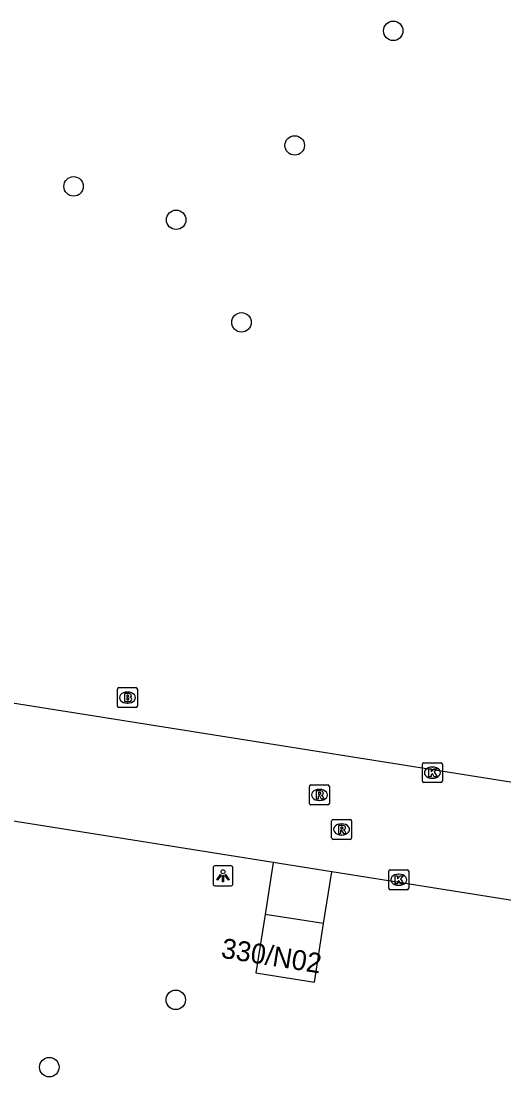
# Model space of a CAD drawing. Extents: x 154324 to 155743, y 382939 to 384183.
# Drawn here: x 155280.3 to 155304.6, y 383376.4 to 383429.5 of the extents above; entities that cross this region are included whole.
import ezdxf

# ---------------------------------------------------------------- set-up
doc = ezdxf.new("R2010")
doc.units = 0
for name, color, linetype in [('IMGEO_Boom', 7, 'Continuous'), ('IMGEO_Brandkraan', 7, 'Continuous'), ('IMGEO_Kolk', 7, 'Continuous'), ('IMGEO_Lichtpunt', 7, 'Continuous'), ('IMGEO_Pand', 7, 'Continuous'), ('IMGEO_Pand_nummerreeks', 7, 'Continuous'), ('IMGEO_Rijbaan_lokaal_gesloten', 7, 'Continuous'), ('IMGEO_Rioolput', 7, 'Continuous'), ('IMGEO_Voetpad_open', 7, 'Continuous')]:
    doc.layers.add(name, color=color, linetype=linetype)

msp = doc.modelspace()

# ---------------------------------------------------------------- linework, layer by layer
at = {"layer": 'IMGEO_Boom'}
for centre in [(155299.009, 383428.969), (155294.061, 383423.212), (155282.955, 383421.154), (155288.107, 383419.476), (155291.389, 383414.322), (155288.087, 383380.284), (155281.736, 383376.901)]:
    msp.add_circle(centre, 0.489, dxfattribs=at)
at = {"layer": 'IMGEO_Brandkraan'}
for p, q in [((155285.236, 383395.968), (155286.088, 383395.968)), ((155285.161, 383395.042), (155285.161, 383395.894)), ((155285.649, 383395.748), (155285.674, 383395.748)), ((155286.162, 383395.894), (155286.162, 383395.042)), ((155286.088, 383394.968), (155285.236, 383394.968)), ((155285.672, 383395.188), (155285.647, 383395.188))]:
    msp.add_line(p, q, dxfattribs=at)
for points in [[(155285.236, 383395.968), (155286.088, 383395.968)], [(155285.161, 383395.042), (155285.161, 383395.894)], [(155285.509, 383395.668), (155285.509, 383395.268), (155285.722, 383395.268)], [(155285.74, 383395.668), (155285.509, 383395.668)], [(155285.688, 383395.587), (155285.634, 383395.587), (155285.634, 383395.511)], [(155285.634, 383395.511), (155285.687, 383395.511)], [(155285.696, 383395.435), (155285.634, 383395.435), (155285.634, 383395.354)], [(155286.162, 383395.894), (155286.162, 383395.042)], [(155286.088, 383394.968), (155285.236, 383394.968)], [(155285.634, 383395.354), (155285.696, 383395.354)]]:
    msp.add_lwpolyline(points, dxfattribs=at)
for centre, radius, start, end in [((155285.238, 383395.892), 0.0765, 91.552, 178.448), ((155285.238, 383395.892), 0.0765, 91.552, 178.448), ((155286.086, 383395.892), 0.0765, 1.552, 88.448), ((155286.086, 383395.892), 0.0765, 1.552, 88.448), ((155285.689, 383395.549), 0.0379, 267.8285, 90.9355), ((155285.697, 383395.394), 0.0404, 269.8759, 90.5077), ((155285.744, 383395.523), 0.145, 59.4692, 91.5367), ((155285.769, 383395.57), 0.0922, 285.5137, 58.1501), ((155285.774, 383395.378), 0.105, 301.3115, 78.989), ((155285.238, 383395.044), 0.0765, 181.552, 268.448), ((155285.238, 383395.044), 0.0765, 181.552, 268.448), ((155285.728, 383395.519), 0.251, 268.6676, 293.5347), ((155286.086, 383395.044), 0.0765, 271.552, 358.448), ((155286.086, 383395.044), 0.0765, 271.552, 358.448)]:
    msp.add_arc(centre, radius, start, end, dxfattribs=at)
for centre, major_axis, ratio, start_param, end_param in [((155285.648, 383395.468), (-0.387, 0.002), 0.722429, 4.712389, 7.853982), ((155285.673, 383395.468), (-0.39, 0.002), 0.717154, 1.570796, 4.712389)]:
    msp.add_ellipse(centre, major_axis=major_axis, ratio=ratio, start_param=start_param, end_param=end_param, dxfattribs=at)
at = {"layer": 'IMGEO_Kolk'}
for p, q in [((155300.473, 383391.27), (155300.473, 383392.122)), ((155300.548, 383392.196), (155301.4, 383392.196)), ((155300.961, 383391.976), (155300.986, 383391.976)), ((155301.474, 383392.122), (155301.474, 383391.27)), ((155301.4, 383391.196), (155300.548, 383391.196)), ((155300.984, 383391.416), (155300.959, 383391.416)), ((155298.784, 383385.89), (155298.784, 383386.742)), ((155298.859, 383386.816), (155299.711, 383386.816)), ((155299.272, 383386.596), (155299.297, 383386.596)), ((155299.785, 383386.742), (155299.785, 383385.89)), ((155299.295, 383386.036), (155299.27, 383386.036)), ((155299.711, 383385.816), (155298.859, 383385.816))]:
    msp.add_line(p, q, dxfattribs=at)
for points in [[(155300.473, 383391.27), (155300.473, 383392.122)], [(155300.548, 383392.196), (155301.4, 383392.196)], [(155300.794, 383391.896), (155300.917, 383391.896), (155300.917, 383391.745), (155301.047, 383391.896), (155301.211, 383391.896), (155301.065, 383391.745), (155301.218, 383391.496), (155301.066, 383391.496), (155300.981, 383391.66), (155300.917, 383391.593), (155300.917, 383391.496), (155300.794, 383391.496), (155300.794, 383391.896)], [(155301.474, 383392.122), (155301.474, 383391.27)], [(155301.4, 383391.196), (155300.548, 383391.196)], [(155298.784, 383385.89), (155298.784, 383386.742)], [(155298.859, 383386.816), (155299.711, 383386.816)], [(155299.105, 383386.516), (155299.228, 383386.516), (155299.228, 383386.365), (155299.358, 383386.516), (155299.522, 383386.516), (155299.376, 383386.365), (155299.529, 383386.116), (155299.377, 383386.116), (155299.292, 383386.28), (155299.228, 383386.213), (155299.228, 383386.116), (155299.105, 383386.116), (155299.105, 383386.516)], [(155299.785, 383386.742), (155299.785, 383385.89)], [(155299.711, 383385.816), (155298.859, 383385.816)]]:
    msp.add_lwpolyline(points, dxfattribs=at)
for centre, start, end in [((155300.55, 383392.12), 91.552, 178.448), ((155300.55, 383392.12), 91.552, 178.448), ((155301.398, 383392.12), 1.552, 88.448), ((155301.398, 383392.12), 1.552, 88.448), ((155300.55, 383391.272), 181.552, 268.448), ((155300.55, 383391.272), 181.552, 268.448), ((155301.398, 383391.272), 271.552, 358.448), ((155301.398, 383391.272), 271.552, 358.448), ((155298.861, 383386.74), 91.552, 178.448), ((155298.861, 383386.74), 91.552, 178.448), ((155299.709, 383386.74), 1.552, 88.448), ((155299.709, 383386.74), 1.552, 88.448), ((155298.861, 383385.892), 181.552, 268.448), ((155298.861, 383385.892), 181.552, 268.448), ((155299.709, 383385.892), 271.552, 358.448), ((155299.709, 383385.892), 271.552, 358.448)]:
    msp.add_arc(centre, 0.0765, start, end, dxfattribs=at)
for centre, major_axis, ratio, start_param, end_param in [((155300.96, 383391.696), (-0.387, 0.002), 0.722429, 4.712389, 7.853982), ((155300.985, 383391.696), (-0.39, 0.002), 0.717154, 1.570796, 4.712389), ((155299.271, 383386.316), (-0.387, 0.002), 0.722429, 4.712389, 7.853982), ((155299.296, 383386.316), (-0.39, 0.002), 0.717154, 1.570796, 4.712389)]:
    msp.add_ellipse(centre, major_axis=major_axis, ratio=ratio, start_param=start_param, end_param=end_param, dxfattribs=at)
at = {"layer": 'IMGEO_Lichtpunt'}
for p, q in [((155290.864, 383387.013), (155290.056, 383387.013)), ((155290.864, 383387.013), (155290.056, 383387.013)), ((155289.962, 383386.918), (155289.962, 383386.111)), ((155289.962, 383386.918), (155289.962, 383386.111)), ((155290.958, 383386.111), (155290.958, 383386.918)), ((155290.958, 383386.111), (155290.958, 383386.918)), ((155290.056, 383386.017), (155290.864, 383386.017)), ((155290.056, 383386.017), (155290.864, 383386.017))]:
    msp.add_line(p, q, dxfattribs=at)
for points in [[(155290.336, 383386.582), (155290.375, 383386.554), (155290.187, 383386.292), (155290.149, 383386.319), (155290.336, 383386.582)], [(155290.438, 383386.534), (155290.485, 383386.534), (155290.485, 383386.212), (155290.438, 383386.212), (155290.438, 383386.534)], [(155290.548, 383386.554), (155290.586, 383386.581), (155290.773, 383386.319), (155290.734, 383386.291), (155290.548, 383386.554)]]:
    msp.add_lwpolyline(points, dxfattribs=at)
msp.add_circle((155290.461, 383386.716), 0.0994, dxfattribs=at)
for centre, start, end in [((155290.056, 383386.918), 90, 180), ((155290.056, 383386.918), 90, 180), ((155290.864, 383386.918), 0, 90), ((155290.864, 383386.918), 0, 90), ((155290.056, 383386.111), 180, 270), ((155290.056, 383386.111), 180, 270), ((155290.864, 383386.111), 270, 0), ((155290.864, 383386.111), 270, 360)]:
    msp.add_arc(centre, 0.0946, start, end, dxfattribs=at)
at = {"layer": 'IMGEO_Pand'}
for points in [[(155292.571, 383384.573), (155292.112, 383381.637), (155295.052, 383381.177), (155295.512, 383384.113)], [(155295.512, 383384.113), (155292.571, 383384.573)]]:
    msp.add_lwpolyline(points, dxfattribs=at)
at = {"layer": 'IMGEO_Rijbaan_lokaal_gesloten'}
for points in [[(155322.727, 383388.39), (155286.115, 383394.2), (155241.462, 383401.286)], [(155292.985, 383387.18), (155280.782, 383389.119), (155238.742, 383395.799)], [(155295.925, 383386.713), (155292.985, 383387.18)], [(155360.426, 383376.464), (155295.925, 383386.713)]]:
    msp.add_lwpolyline(points, dxfattribs=at)
at = {"layer": 'IMGEO_Rioolput'}
for p, q in [((155294.802, 383390.153), (155294.802, 383391.005)), ((155294.877, 383391.079), (155295.729, 383391.079)), ((155295.29, 383390.859), (155295.315, 383390.859)), ((155295.803, 383391.005), (155295.803, 383390.153)), ((155295.313, 383390.299), (155295.288, 383390.299)), ((155295.729, 383390.079), (155294.877, 383390.079)), ((155295.916, 383388.418), (155295.916, 383389.27)), ((155295.991, 383389.344), (155296.843, 383389.344)), ((155296.404, 383389.124), (155296.429, 383389.124)), ((155296.917, 383389.27), (155296.917, 383388.418)), ((155296.427, 383388.564), (155296.402, 383388.564)), ((155296.843, 383388.344), (155295.991, 383388.344))]:
    msp.add_line(p, q, dxfattribs=at)
for points in [[(155294.802, 383390.153), (155294.802, 383391.005)], [(155294.877, 383391.079), (155295.729, 383391.079)], [(155295.391, 383390.777), (155295.139, 383390.779), (155295.139, 383390.379)], [(155295.317, 383390.698), (155295.263, 383390.698), (155295.263, 383390.617)], [(155295.803, 383391.005), (155295.803, 383390.153)], [(155295.139, 383390.379), (155295.263, 383390.379), (155295.263, 383390.541), (155295.274, 383390.541)], [(155295.263, 383390.617), (155295.315, 383390.617)], [(155295.321, 383390.512), (155295.392, 383390.379), (155295.532, 383390.379), (155295.467, 383390.505)], [(155295.729, 383390.079), (155294.877, 383390.079)], [(155295.916, 383388.418), (155295.916, 383389.27)], [(155295.991, 383389.344), (155296.843, 383389.344)], [(155296.917, 383389.27), (155296.917, 383388.418)], [(155296.505, 383389.042), (155296.253, 383389.044), (155296.253, 383388.644)], [(155296.253, 383388.644), (155296.377, 383388.644), (155296.377, 383388.806), (155296.388, 383388.806)], [(155296.431, 383388.963), (155296.377, 383388.963), (155296.377, 383388.882)], [(155296.377, 383388.882), (155296.429, 383388.882)], [(155296.435, 383388.777), (155296.506, 383388.644), (155296.646, 383388.644), (155296.581, 383388.77)], [(155296.843, 383388.344), (155295.991, 383388.344)]]:
    msp.add_lwpolyline(points, dxfattribs=at)
for centre, radius, start, end in [((155294.879, 383391.003), 0.0765, 91.552, 178.448), ((155294.879, 383391.003), 0.0765, 91.552, 178.448), ((155295.323, 383390.602), 0.0964, 77.0061, 93.1865), ((155295.337, 383390.659), 0.0378, 276.6634, 79.6772), ((155295.39, 383390.667), 0.109, 350.3612, 89.416), ((155295.388, 383390.667), 0.112, 277.5842, 350.9817), ((155295.727, 383391.003), 0.0765, 1.552, 88.448), ((155295.727, 383391.003), 0.0765, 1.552, 88.448), ((155294.879, 383390.155), 0.0765, 181.552, 268.448), ((155294.879, 383390.155), 0.0765, 181.552, 268.448), ((155295.273, 383390.488), 0.0533, 26.0293, 88.6989), ((155295.299, 383390.806), 0.19, 274.7715, 282.9687), ((155295.372, 383390.452), 0.108, 29.5134, 73.7905), ((155295.727, 383390.155), 0.0765, 271.552, 358.448), ((155295.727, 383390.155), 0.0765, 271.552, 358.448), ((155295.993, 383389.268), 0.0765, 91.552, 178.448), ((155295.993, 383389.268), 0.0765, 91.552, 178.448), ((155296.841, 383389.268), 0.0765, 1.552, 88.448), ((155296.841, 383389.268), 0.0765, 1.552, 88.448), ((155296.387, 383388.753), 0.0533, 26.0293, 88.6989), ((155296.413, 383389.071), 0.19, 274.7715, 282.9687), ((155296.437, 383388.867), 0.0964, 77.0061, 93.1865), ((155296.451, 383388.924), 0.0378, 276.6634, 79.6772), ((155296.504, 383388.932), 0.109, 350.3612, 89.416), ((155296.502, 383388.932), 0.112, 277.5842, 350.9817), ((155296.486, 383388.717), 0.108, 29.5134, 73.7905), ((155295.993, 383388.42), 0.0765, 181.552, 268.448), ((155295.993, 383388.42), 0.0765, 181.552, 268.448), ((155296.841, 383388.42), 0.0765, 271.552, 358.448), ((155296.841, 383388.42), 0.0765, 271.552, 358.448)]:
    msp.add_arc(centre, radius, start, end, dxfattribs=at)
for centre, major_axis, ratio, start_param, end_param in [((155295.289, 383390.579), (-0.387, 0.002), 0.722429, 4.712389, 7.853982), ((155295.314, 383390.579), (-0.39, 0.002), 0.717154, 1.570796, 4.712389), ((155296.403, 383388.844), (-0.387, 0.002), 0.722429, 4.712389, 7.853982), ((155296.428, 383388.844), (-0.39, 0.002), 0.717154, 1.570796, 4.712389)]:
    msp.add_ellipse(centre, major_axis=major_axis, ratio=ratio, start_param=start_param, end_param=end_param, dxfattribs=at)
at = {"layer": 'IMGEO_Voetpad_open'}
for points in [[(155292.985, 383387.18), (155292.571, 383384.573)], [(155295.512, 383384.113), (155295.925, 383386.713)]]:
    msp.add_lwpolyline(points, dxfattribs=at)

# ---------------------------------------------------------------- texts
at = {"layer": 'IMGEO_Pand_nummerreeks'}
msp.add_text('330/N02', height=1, rotation=350.9129, dxfattribs=at).set_placement((155290.325, 383382.406))

doc.saveas('drawing.dxf')
